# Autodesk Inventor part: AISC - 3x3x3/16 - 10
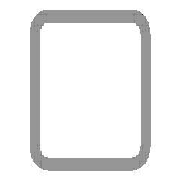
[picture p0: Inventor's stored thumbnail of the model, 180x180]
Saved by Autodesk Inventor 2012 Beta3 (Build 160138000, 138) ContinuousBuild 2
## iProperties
_CCFamilyMember: 9
_CCFamilyDisplayName: ANSI AISC (Square) - Tube
_FrameMemberDoc: Frame Member File
_Version: 15.0.0
_GetPNFromCC: 1
Created: 2011-01
Part Number: AISC - 3x3x3/16 - 10
Material: Steel, Mild
Description: Tube
Document SubType Name: Modeling
Standard: ANSI
Designer: Beta-8540w
Standards Organization: ANSI
Language: en-US
Size Designation: 3x3x3/16
Categories: <MemberInstance><Categories><Category DisplayName="Structural Shapes" InternalName="089c4875-fa83-4c05-b084-43b9cc11f5ed" Mnemonic="GRDR"><CategoryParameter Dis
Stock Number: 3x3x3/16
Density: 7.86 g/cm^3
IsCustomPart: 1
G_L: 10.000 in
G_W: 3.000 in
G_H: 3.000 in
Author: Beta-8540w
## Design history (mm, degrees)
node "Start plane"
node "End plane"
sketch "Sketch"
  geometry: L1 (-38.1, -28.575)-(-38.1, 28.575); L2 (-28.575, 38.1)-(28.575, 38.1); L3 (38.1, 28.575)-(38.1, -28.575); L4 (28.575, -38.1)-(-28.575, -38.1); L5 (-28.575, 33.337)-(28.575, 33.338); L6 (33.338, 28.575)-(33.338, -28.575); L7 (28.575, -33.337)-(-28.575, -33.338); L8 (-33.338, -28.575)-(-33.338, 28.575); L9 (0, 56.102)-(0, -56.102) reference; L10 (-56.102, 0)-(56.102, 0) reference; A1 r 9.525 centre (-28.575, -28.575) between (-38.1, -28.575) and (-28.575, -38.1); A2 r 9.525 centre (-28.575, 28.575) between (-28.575, 38.1) and (-38.1, 28.575); A3 r 9.525 centre (28.575, 28.575) between (38.1, 28.575) and (28.575, 38.1); A4 r 9.525 centre (28.575, -28.575) between (28.575, -38.1) and (38.1, -28.575); A5 r 4.763 centre (-28.575, 28.575) between (-28.575, 33.337) and (-33.338, 28.575); A6 r 4.763 centre (28.575, 28.575) between (33.338, 28.575) and (28.575, 33.338); A7 r 4.763 centre (28.575, -28.575) between (28.575, -33.337) and (33.338, -28.575); A8 r 4.763 centre (-28.575, -28.575) between (-33.338, -28.575) and (-28.575, -33.338)
  constraints: 16 end point, 16 point on circle, 8 centre point, 8 tangent, 4 parallel, 3 equal radius, 2 perpendicular, 7 other
  dimensions: "d10" = 76.2 distance between parallel lines of L2 L4 (= G_H); "d11" = 76.2 distance between parallel lines of L1 L3 (= G_W); "d12" = 4.7625 distance between parallel lines of L3 L6 (= G_T); "d15" = 38.1 distance between parallel lines of L2 L10 (= 0.5 x d10); "d16" = 38.1 distance between parallel lines of L9 L3 (= 0.5 x d11); "d17" = 9.525 radius of A1 (= G_IR)
extrude "Body" new body sketch "Sketch" stored distance "d3" = 254 (= G_L); taper "d4" = 0 deg
node "Driven Length"
  sketch "Sketch3"
    geometry: L1 (0, 0)-(10, 0) reference
    constraints: 2 end point, 1 horizontal
  workplane "Work Plane3"
  sketch "Sketch4"
    geometry: L1 (-2, 0)-(12, 0) reference; L2 (-2, 254)-(12, 254) reference
    dimensions: "d19" = 254 distance between parallel lines of L1 L2 (derived)
body "Solid1"
other parameters: "G_W" = 76.2 [user parameter; used in 1 equation term], "G_H" = 76.2 [user parameter; used in 1 equation term], "G_T" = 4.7625 [user parameter; used in 1 equation term], "G_IR" = 9.525 [user parameter; used in 1 equation term], "G_L" = 254 (= d19) [user parameter; used in 1 equation term], "G_OFFSET_START" = 0 [user parameter; used in 1 equation term], "G_OFFSET_END" = 0 [user parameter; used in 1 equation term], "d13" = 0 (computed from G_OFFSET_START), "d14" = 254 (= G_OFFSET_END + B_L), "B_L" = 254 [user parameter; used in 1 equation term], "d18" = 90 deg
